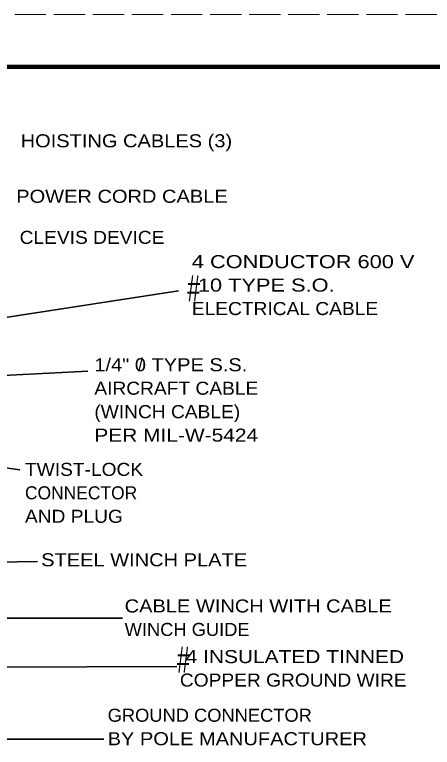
# Model space of a CAD drawing. Extents: x -1 to 679, y 0 to 440.
# Drawn here: x 456.1 to 536.2, y 299.1 to 439.6 of the extents above; entities that cross this region are included whole.
import ezdxf
from ezdxf.enums import TextEntityAlignment as Align

# ---------------------------------------------------------------- set-up
doc = ezdxf.new("R2010")
doc.units = 0
doc.linetypes.add('LONG_DASHED', pattern=[7.5, 6, -1.5])
doc.layers.add('1', color=7, linetype='Continuous', lineweight=35)
doc.layers.add('61', color=7, linetype='Continuous', lineweight=35)

msp = doc.modelspace()

# ---------------------------------------------------------------- linework, layer by layer
at = {"layer": '1'}
for p, q in [((421.756, 376.569), (487.534, 386.706)), ((417.825, 368.494), (470.128, 371.287)), ((419.738, 357.745), (457.08, 352.325)), ((440.988, 334.444), (460.448, 334.79)), ((420.502, 323.887), (476.777, 323.887)), ((448.274, 314.493), (487.22, 314.649)), ((449.829, 300.666), (473.193, 300.666))]:
    msp.add_line(p, q, dxfattribs=at)
at = {"layer": '61', "linetype": 'LONG_DASHED', "lineweight": 13}
msp.add_line((-1.425, 439.645), (678.595, 439.645), dxfattribs=at)
at = {"layer": '61', "lineweight": 158}
msp.add_lwpolyline([(667.615, 429.645), (28.575, 429.645), (28.575, 9.625)], dxfattribs=at)

# ---------------------------------------------------------------- texts
at = {"layer": '1'}
for s, height, width, p in [('HOISTING CABLES (3)', 2.5, 1.15, (477.514, 414.202)), ('POWER CORD CABLE', 2.5, 1.15, (476.663, 403.559)), ('CLEVIS DEVICE', 2.5, 1.1, (470.917, 395.683)), ('#', 5, 0.65, (490.424, 384.675)), ('STEEL WINCH PLATE', 2.5, 1.15, (480.919, 333.845)), ('#', 5, 0.65, (488.425, 313.44))]:
    msp.add_text(s, height=height, dxfattribs=dict(at, width=width)).set_placement(p, align=Align.CENTER)
for s, width, p in [('4 CONDUCTOR 600 V', 1.25, (490.069, 391.027)), (' 10 TYPE S.O.', 1.25, (490.069, 386.527)), ('ELECTRICAL CABLE', 1.1, (490.069, 382.027)), ('1/4" 0 TYPE S.S.', 1.15, (471.36, 371.248)), ('AIRCRAFT CABLE', 1.1, (471.36, 366.748)), ('(WINCH CABLE)', 1.1, (471.36, 362.248)), ('PER MIL-W-5424', 1.2, (471.36, 357.748)), ('TWIST-LOCK', 1.1, (458.043, 351.185)), ('AND PLUG', 1.1, (458.043, 342.185)), ('CABLE WINCH WITH CABLE', 1.15, (477.177, 324.985)), ('WINCH GUIDE', 1.05, (477.177, 320.485)), (' 4 INSULATED TINNED', 1.2, (487.774, 315.273)), ('COPPER GROUND WIRE', 1.1, (487.774, 310.773)), ('GROUND CONNECTOR', 1.05, (473.916, 304.027)), ('BY POLE MANUFACTURER', 1.15, (473.916, 299.527))]:
    msp.add_text(s, height=2.5, dxfattribs=dict(at, width=width)).set_placement(p)
msp.add_text('/', height=2.5, dxfattribs=at).set_placement((480.231, 371.267), align=Align.CENTER)
msp.add_text('CONNECTOR', height=2.5, dxfattribs=at).set_placement((458.043, 346.685))

doc.saveas('drawing.dxf')
